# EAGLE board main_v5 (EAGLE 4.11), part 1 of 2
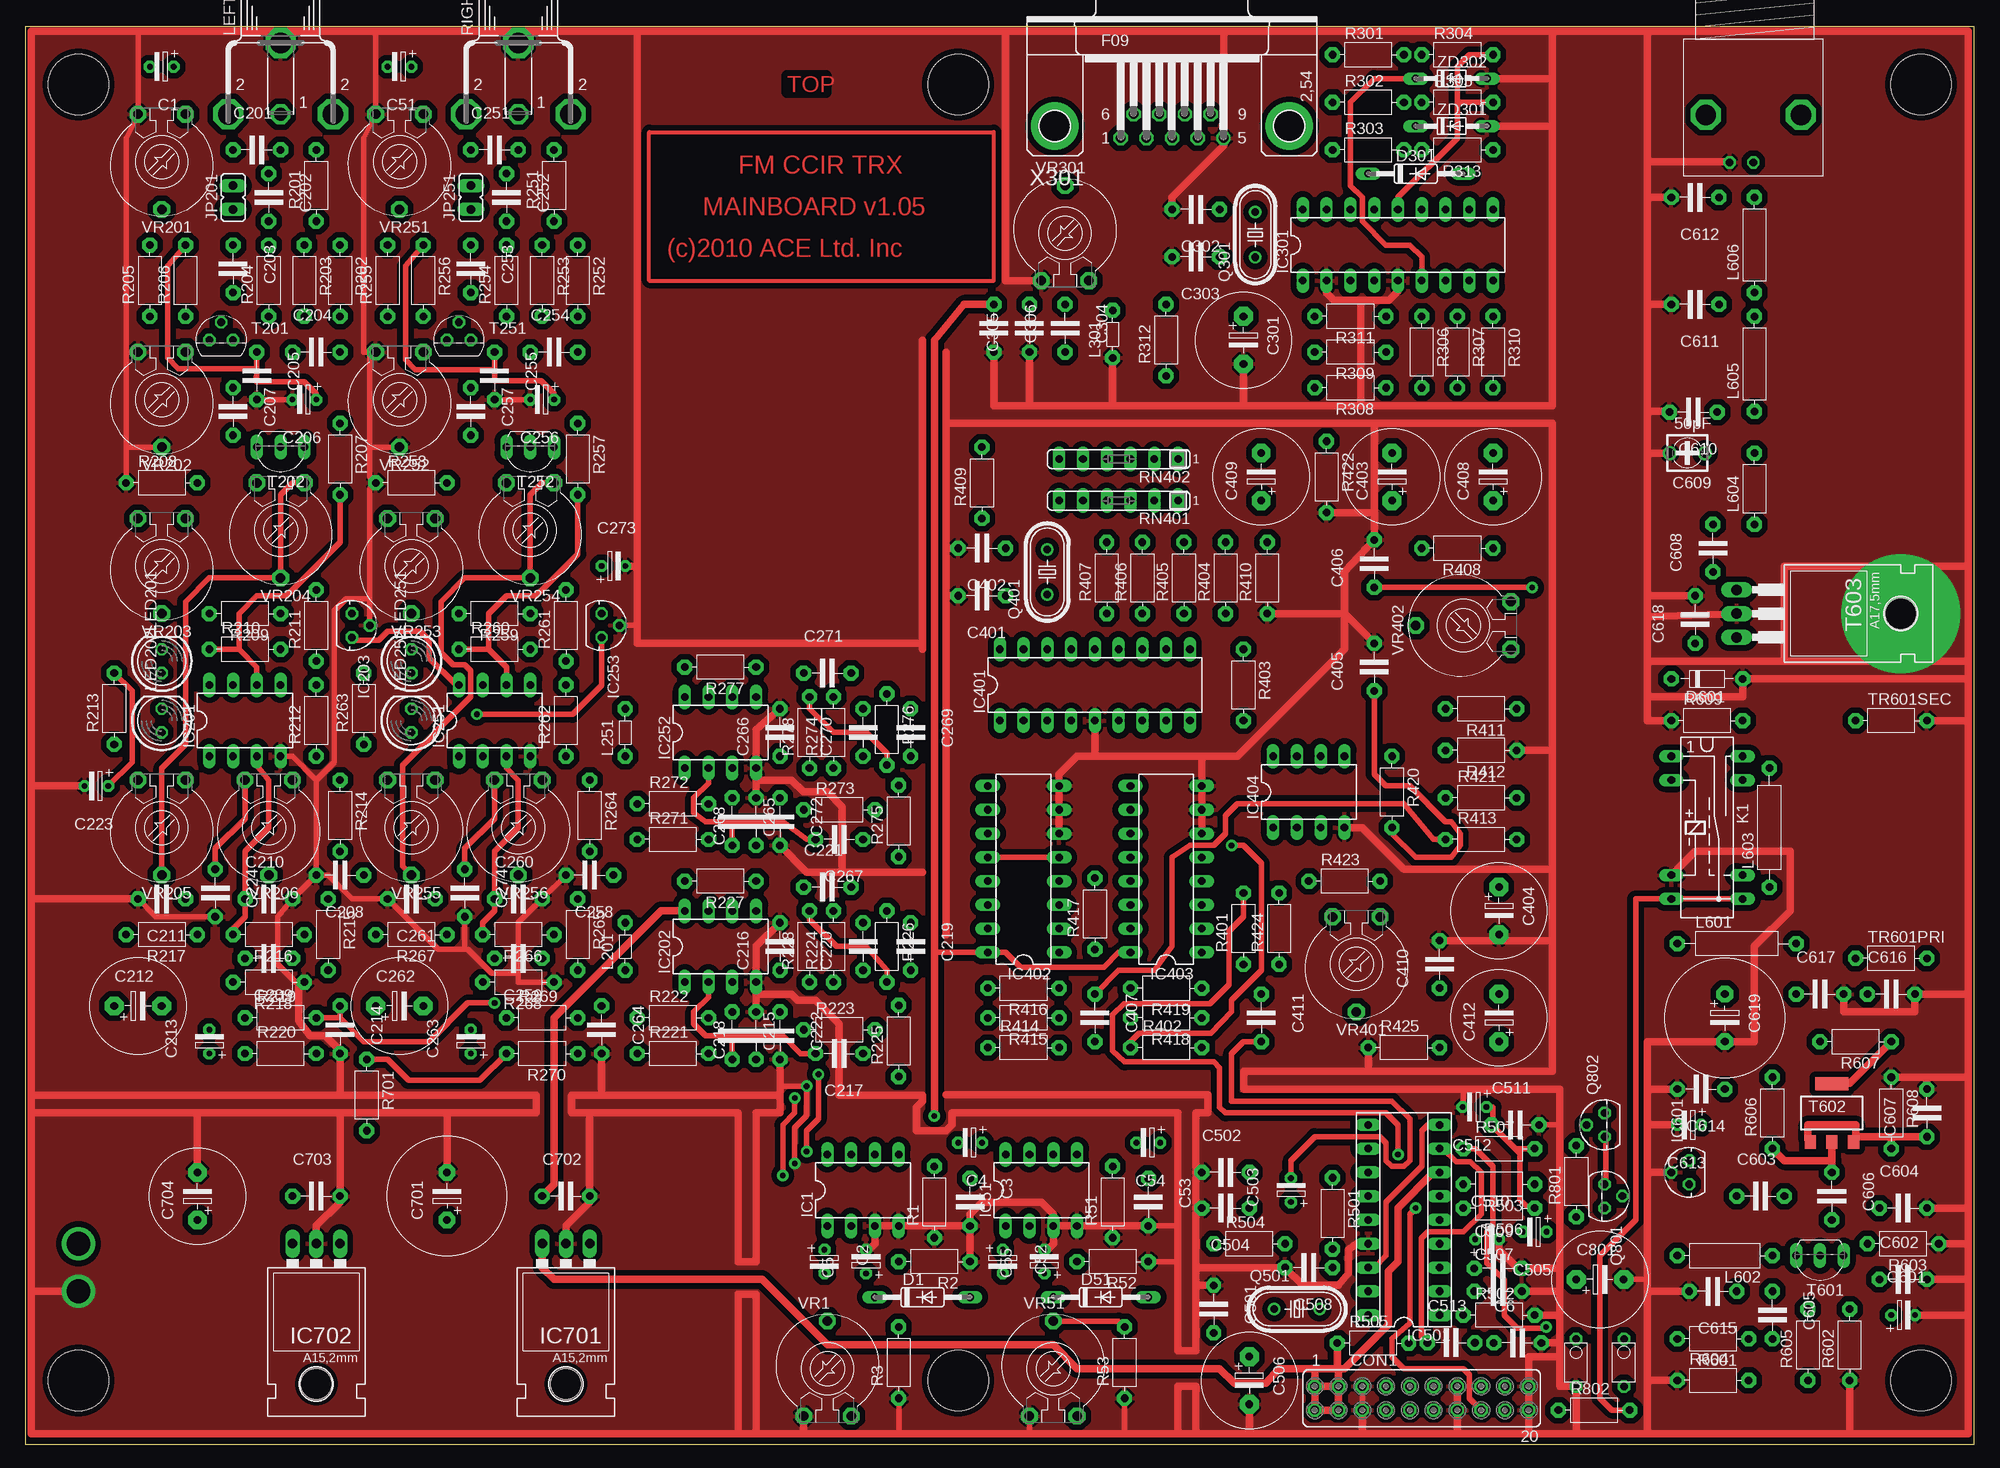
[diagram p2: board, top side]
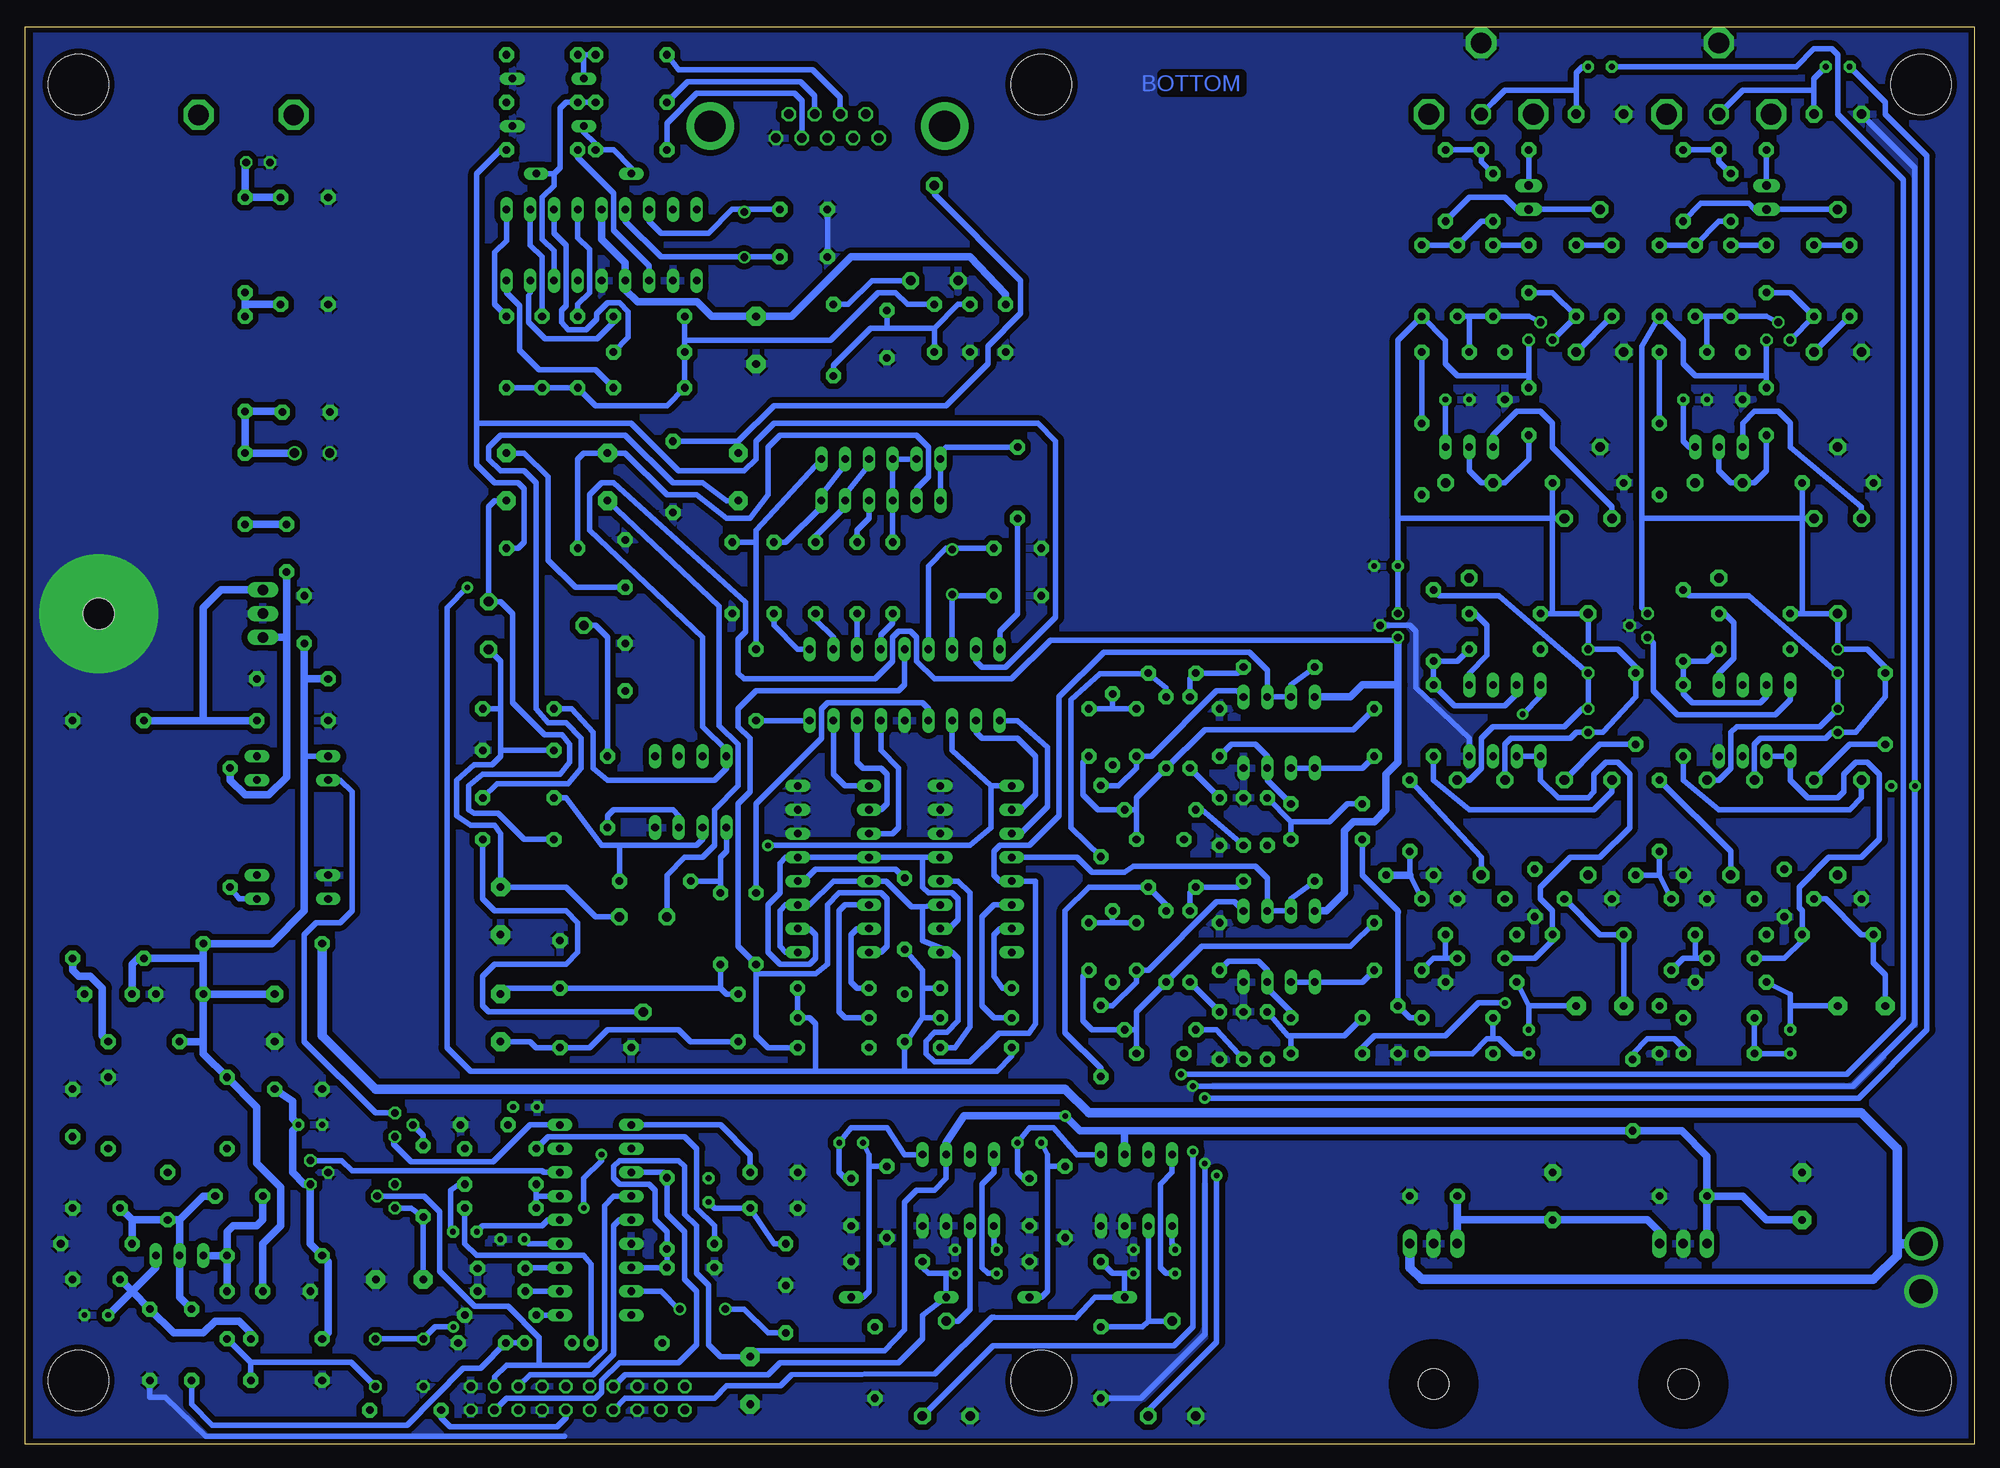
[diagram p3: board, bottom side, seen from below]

Size 208.26 x 151.44 mm. Coordinates in mm from the lower left corner, seen from the top.
Outline: 0,0 208.26,0 208.26,151.44 0,151.44 0,0
Copper layers (1*16): Top 0.035mm / dielectric 1.5mm / Bottom 0.035mm
Design rules "TRIDA5": minimum track width 10mil, minimum drill 24mil, track to track 12mil, track to pad 9mil, pad to pad 11mil, via to via 12mil, smd to smd 12mil, copper to edge 8mil, drill to drill 12mil, minimum pad ring 10mil, minimum via ring 12mil, stop-mask expansion 4mil, vias tented up to drill 0mil, thermal gap 10mil
Holes 6.45 mm at 99.69,6.82 5.71,6.82 202.56,145.25 202.56,6.82 5.71,145.25 99.69,145.25

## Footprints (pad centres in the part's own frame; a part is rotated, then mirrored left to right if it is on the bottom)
ES-2,5 = drill 0.61 pad 1.27 octagon: 1 -1.27,0; 2 1.27,0
C-5 = drill 0.813 pad 1.6 octagon: 1 -2.54,0; 2 2.54,0
ES-5 = drill 0.813 pad 2.007 octagon: 1 -2.54,0; 2 2.54,0
3008 = drill 1 round: + -1.875,0; - 1.875,0
ES-5L = drill 0.813 pad 1.778 octagon: 1 0,0; 2 5.08,0
FE10-2 = drill 0.914 octagon: 1 -11.43,1.27; 2 -11.43,-1.27; 3 -8.89,1.27; 4 -8.89,-1.27; 5 -6.35,1.27; 6 -6.35,-1.27; 7 -3.81,1.27; 8 -3.81,-1.27; 9 -1.27,1.27; 10 -1.27,-1.27; 11 1.27,1.27; 12 1.27,-1.27; 13 3.81,1.27; 14 3.81,-1.27; 15 6.35,1.27; 16 6.35,-1.27; 17 8.89,1.27; 18 8.89,-1.27; 19 11.43,1.27; 20 11.43,-1.27
DO35-10 = drill 0.813 long: A 5.08,0; C -5.08,0
D-7,5 = drill 0.813 pad 1.6 octagon: 1 -3.81,0; 2 3.81,0
DIL08 = drill 0.813 long: 1 -3.81,-3.81; 2 -1.27,-3.81; 3 1.27,-3.81; 4 3.81,-3.81; 5 3.81,3.81; 6 1.27,3.81; 7 -1.27,3.81; 8 -3.81,3.81
78LXX = drill 0.813 octagon: GND 0,1.905; IN 1.27,0; OUT -1.27,0
DIL18 = drill 0.813 long: 1 -10.16,-3.81; 2 -7.62,-3.81; 3 -5.08,-3.81; 4 -2.54,-3.81; 5 0,-3.81; 6 2.54,-3.81; 7 5.08,-3.81; 8 7.62,-3.81; 9 10.16,-3.81; 10 10.16,3.81; 11 7.62,3.81; 12 5.08,3.81; 13 2.54,3.81; 14 0,3.81; 15 -2.54,3.81; 16 -5.08,3.81; 17 -7.62,3.81; 18 -10.16,3.81
DIL16 = drill 0.813 long: 1 -8.89,-3.81; 2 -6.35,-3.81; 3 -3.81,-3.81; 4 -1.27,-3.81; 5 1.27,-3.81; 6 3.81,-3.81; 7 6.35,-3.81; 8 8.89,-3.81; 9 8.89,3.81; 10 6.35,3.81; 11 3.81,3.81; 12 1.27,3.81; 13 -1.27,3.81; 14 -3.81,3.81; 15 -6.35,3.81; 16 -8.89,3.81
SOCKED-18 = drill 0.813 long: 1 -10.16,-3.81; 2 -7.62,-3.81; 3 -5.08,-3.81; 4 -2.54,-3.81; 5 0,-3.81; 6 2.54,-3.81; 7 5.08,-3.81; 8 7.62,-3.81; 9 10.16,-3.81; 10 10.16,3.81; 11 7.62,3.81; 12 5.08,3.81; 13 2.54,3.81; 14 0,3.81; 15 -2.54,3.81; 16 -5.08,3.81; 17 -7.62,3.81; 18 -10.16,3.81
78XXL = drill 1.016 long: GND 0,-3.81; IN -2.54,-3.81; OUT 2.54,-3.81 | hole 3.302: 0,11.176
JP1 = drill 0.914 long: 1 0,-1.27; 2 0,1.27
RR1U = drill 0.813 long: 1 -7.62,-3.81; 2 -5.08,-3.81; 6 5.08,-3.81; 7 7.62,-3.81; 8 7.62,3.81; 9 5.08,3.81; 13 -5.08,3.81; 14 -7.62,3.81
L-5 = drill 0.813 pad 1.6 octagon: 1 -2.54,0; 2 2.54,0
L-12,5 = drill 0.813 pad 1.6 octagon: 1 -6.35,0; 2 6.35,0
L-10 = drill 0.813 pad 1.6 octagon: 1 -5.08,0; 2 5.08,0
L-7,5 = drill 0.813 pad 1.6 octagon: 1 -3.81,0; 2 3.81,0
LED5MM = drill 0.813 octagon: A -1.27,0; K 1.27,0
TOBU3 = drill 1.397 octagon: 1 0,-2.54 | drill 2.21 octagon: 2 5.588,-2.54; 2@1 -5.588,-2.54; 2@2 0,5.08
HC49/S = drill 0.813 round: 1 -2.413,0; 2 2.413,0
HC49U-V = drill 0.813 round: 1 -2.413,0; 2 2.413,0
TO92 = drill 0.813 octagon: 1 1.27,0; 2 0,1.905; 3 -1.27,0
R-7,5 = drill 0.813 pad 1.6 octagon: 1 -3.81,0; 2 3.81,0
SIL6 = drill 0.813 long: 1 -6.35,0; 2 -3.81,0; 3 -1.27,0; 4 1.27,0; 5 3.81,0; 6 6.35,0
TO92-EBC = drill 0.813 long: B 0,-1.27; C -2.54,-1.27; E 2.54,-1.27
TO92-CEB = drill 0.813 long: B -2.54,0; C 2.54,0; E 0,0
SOT223 = smd 1.2 x 1.4: 1 -2.311,-3.099; 2 0,-3.099; 3 2.311,-3.099 | smd 3.5 x 1.4: 4 0,3.099
TO220AH = drill 1.118 long: 1 -2.54,-6.35; 2 0,-6.35; 3 2.54,-6.35 | hole 3.302: 0,11.176
BNC-Z50RW = drill 2.184 octagon: P$1 0,-5.08; P$2 0,5.08 | drill 0.813 octagon: P$3 5.08,0; P$4 5.08,-2.54
BB1X = drill 0.813 octagon: P$1 -2.54,0; P$2 2.54,0
PT-10 = drill 1.016 pad 1.778 octagon: 1 -2.54,-5.08; 2 2.54,-5.08; 3 0,5.08
F09HP = drill 1.016 octagon: 1 -5.486,-1.27; 2 -2.743,-1.27; 3 0,-1.27; 4 2.743,-1.27; 5 5.486,-1.27; 6 -4.115,1.27; 7 -1.372,1.27; 8 1.372,1.27; 9 4.115,1.27 | drill 3.302 pad 5.08 round: G1 -12.522,0; G2 12.522,0
DO34Z7 = drill 0.813 long: A 3.81,0; C -3.81,0

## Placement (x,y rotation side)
C1  0,47uF  [ES-2,5]  14.6,147.16 180 top
C2  10uF  [ES-2,5]  85.4,19.52 270 top
C3  47nF  [C-5]  100.96,25.87 270 top
C4  4,7uF  [ES-2,5]  100.96,32.22 180 top
C5  0,1uF  [ES-2,5]  89.85,19.52 90 top
C6  100nF  [C-5]  159.46,10.83 0 top
C51  0,47uF  [ES-2,5]  40,147.16 180 top
C52  10uF  [ES-2,5]  104.45,19.52 270 top
C53  47nF  [C-5]  120.01,25.87 270 top
C54  4,7uF  [ES-2,5]  120.01,32.22 180 top
C55  0,1uF  [ES-2,5]  108.9,19.52 90 top
C201  4,7n  [C-5]  24.76,138.26 0 top
C202  470n  [C-5]  26.03,133.19 270 top
C203  4,7n  [C-5]  22.22,125.56 270 top
C204  330n  [C-5]  31.11,116.67 0 top
C205  10n  [C-5]  24.76,114.14 270 top
C206  10uF  [ES-2,5]  29.84,111.59 180 top
C207  22n  [C-5]  22.22,110.33 270 top
C208  330p  [C-5]  33.65,60.79 180 top
C209  470p  [C-5]  26.03,51.9 180 top
C210  82p  [C-5]  26.03,58.25 0 top
C211  10n  [C-5]  14.6,58.25 180 top
C212  220uF  [ES-5]  12.06,46.82 0 top
C213  220uF  [ES-2,5]  19.68,43.01 90 top
C214  560p  [C-5]  33.65,44.28 270 top
C215  2n7  [C-5]  75.56,43.65 270 top
C216  22p  [C-5]  80.64,53.17 90 top
C217  4n7  [C-5]  86.99,41.74 180 top
C218  10n  [C-5]  78.1,43.65 90 top
C219  270p  [C-5]  94.61,53.17 270 top
C220  270p  [C-5]  89.53,53.17 90 top
C221  560p  [C-5]  85.72,59.52 0 top
C222  100n  [C-5]  80.64,43.65 270 top
C223  220uF  [ES-2,5]  7.62,70.32 180 top
C224  10n  [C-5]  20.31,58.89 270 top
C251  4,7n  [C-5]  50.16,138.26 0 top
C252  470n  [C-5]  51.43,133.19 270 top
C253  4,7n  [C-5]  47.62,125.56 270 top
C254  330n  [C-5]  56.51,116.67 0 top
C255  10n  [C-5]  50.16,114.14 270 top
C256  10uF  [ES-2,5]  55.24,111.59 180 top
C257  22n  [C-5]  47.62,110.33 270 top
C258  330p  [C-5]  60.32,60.79 180 top
C259  470p  [C-5]  52.7,51.9 180 top
C260  82p  [C-5]  52.7,58.25 0 top
C261  10n  [C-5]  41.27,58.25 180 top
C262  220uF  [ES-5]  40,46.82 0 top
C263  220uF  [ES-2,5]  47.62,43.01 90 top
C264  560p  [C-5]  61.59,44.28 270 top
C265  2n7  [C-5]  75.56,66.51 270 top
C266  22p  [C-5]  80.64,76.04 90 top
C267  4n7  [C-5]  86.99,64.61 180 top
C268  10n  [C-5]  78.1,66.51 90 top
C269  270p  [C-5]  94.61,76.04 270 top
C270  270p  [C-5]  89.53,76.04 90 top
C271  560p  [C-5]  85.72,82.39 0 top
C272  100n  [C-5]  80.64,66.51 270 top
C273  220uF  [ES-2,5]  62.86,93.81 0 top
C274  10n  [C-5]  46.98,58.89 270 top
C301  220uF  [ES-5]  130.17,117.95 270 top
C302  27p  [C-5]  125.09,131.91 180 top
C303  27p  [C-5]  125.09,126.84 180 top
C304  10nF  [C-5]  111.12,119.22 270 top
C305  22nF  [C-5]  107.31,119.22 90 top
C306  100nF  [C-5]  103.5,119.22 270 top
C401  47p  [C-5]  102.23,90.64 180 top
C402  47p  [C-5]  102.23,95.72 180 top
C403  100uF  [ES-5]  146.04,103.34 90 top
C404  100uF  [ES-5]  157.47,56.98 270 top
C405  22p  [C-5]  144.14,83.02 90 top
C406  82p  [C-5]  144.14,94.07 90 top
C407  100nF  [C-5]  114.3,45.55 270 top
C408  100uF  [ES-5]  156.84,103.34 90 top
C409  100uF  [ES-5]  132.07,103.34 90 top
C410  270p  [C-5]  151.12,51.27 90 top
C411  100nF  [C-5]  132.07,45.55 270 top
C412  220uF  [ES-5]  157.47,45.55 90 top
C501  22pF  [C-5]  126.99,14.44 270 top
C502  10nF  [C-5]  128.27,29.05 0 top
C503  0.22uF  [ES-2,5]  135.25,27.14 90 top
C504  100pF  [C-5]  128.27,25.23 180 top
C505  10uF  [ES-2,5]  161.28,22.7 180 top
C506  220uF  [ES-5]  130.81,6.82 270 top
C507  2.2nF  [C-5]  157.38,16.34 0 top
C508  100nF  [C-5]  137.16,18.89 180 top
C509  10nF  [C-5]  157.38,18.79 0 top
C510  47uF  [ES-2,5]  156.2,21.9 0 top
C511  100pF  [C-5]  159.22,34.12 0 top
C512  0.47uF  [ES-2,5]  154.86,36.03 180 top
C513  1nF  [C-5]  152.36,10.85 0 top
C601  10uF  [ES-2,5]  200.66,13.8 0 top
C602  10nF  [C-5]  200.66,17.62 0 top
C603  15pF  [C-5]  185.41,26.5 0 top
C604  10pF  [C-5]  200.66,25.23 0 top
C605  1nF  [C-5]  186.69,13.8 270 top
C606  22pF  [C-5]  193.03,26.5 270 top
C607  10nF  [C-5]  203.19,35.39 90 top
C608  10nF  [C-5]  180.34,95.72 90 top
C609  50pF  [3008]  177.6,105.88 180 top
C610  47pF  [C-5]  178.24,110.26 180 top
C611  33pF  [C-5]  178.43,121.76 180 top
C612  15pF  [C-5]  178.43,133.19 180 top
C613  10uF  [ES-2,5]  177.79,34.12 180 top
C614  10nF  [C-5]  179.06,37.93 180 top
C615  100nF  [C-5]  180.34,16.34 180 top
C616  10nF  [C-5]  199.38,48.09 0 top
C617  10nF  [C-5]  191.76,48.09 0 top
C618  10nF  [C-5]  178.43,88.1 90 top
C619  470uF  [ES-5L]  181.6,48.09 270 top
C701  470uF  [ES-5L]  45.08,23.96 90 top
C702  10n  [C-5]  57.78,26.5 0 top
C703  100nF  [C-5]  31.11,26.5 0 top
C704  220uF  [ES-5]  18.41,26.5 90 top
C801  330uF  [ES-5]  168.27,17.62 0 top
CON1  [FE10-2]  149.22,4.92 0 top
D1  1N4148  [DO35-10]  95.88,15.71 0 top
D51  1N4148  [DO35-10]  114.93,15.71 0 top
D301  1N4148  [DO35-10]  148.59,135.72 0 top
D601  SB260  [D-7,5]  179.7,81.75 180 top
IC1  LM386N  [DIL08]  89.53,27.14 0 top
IC51  LM386N  [DIL08]  108.58,27.14 0 top
IC201  TLC272P  [DIL08]  23.49,77.31 0 top
IC202  TLC272P  [DIL08]  74.29,53.17 0 top
IC203  78L05  [78LXX]  34.92,87.47 270 top
IC251  TLC272P  [DIL08]  50.16,77.31 0 top
IC252  TLC272P  [DIL08]  74.29,76.04 0 top
IC253  78L05  [78LXX]  61.59,87.47 270 top
IC301  MRDS192  [DIL18]  146.68,128.1 0 top
IC401  PIC18F1220-I/P  [DIL18]  114.3,81.12 0 top
IC402  74HC4053  [DIL16]  106.67,61.43 90 top
IC403  74HC4053  [DIL16]  121.91,61.43 90 top
IC404  TLC272P  [DIL08]  137.16,69.69 0 top
IC501  SAA1057  [SOCKED-18]  147.31,23.96 90 top
IC601  LM78L09  [78LXX]  177.79,29.05 90 top
IC701  7812  [78XXL]  57.78,17.62 180 top
IC702  7805  [78XXL]  31.11,17.62 180 top
JP201  [JP1]  22.22,133.19 0 top
JP251  [JP1]  47.62,133.19 0 top
K1  DIP05-1C90-51L  [RR1U]  179.7,65.88 270 top
L201  15mH  [L-5]  64.13,53.17 90 top
L251  15mH  [L-5]  64.13,76.04 90 top
L301  330uH  [L-5]  116.2,118.58 90 top
L601  1uH  [L-12,5]  182.88,53.49 0 top
L602  3,5z@7mm  [L-10]  181.6,20.16 180 top
L603  1uH  [L-12,5]  186.37,65.88 90 top
L604  2,5z@6mm  [L-7,5]  184.78,102.07 90 top
L605  3,5z@6mm  [L-10]  184.78,115.41 90 top
L606  3,5z@6mm  [L-10]  184.78,128.1 90 top
LED201  [LED5MM]  14.6,83.66 90 top
LED202  [LED5MM]  14.6,77.31 90 top
LED251  [LED5MM]  41.27,83.66 90 top
LED252  [LED5MM]  41.27,77.31 90 top
LEFT  CON2  [TOBU3]  27.3,144.61 0 top
Q301  4.332  [HC49/S]  131.44,129.22 90 top
Q401  7.3728  [HC49U-V]  109.21,93.18 90 top
Q501  4MHz  [HC49U-V]  135.88,14.44 0 top
Q801  BC547A  [TO92]  168.75,26.5 270 top
Q802  BC547A  [TO92]  168.75,34.12 90 top
R1  2k2  [R-7,5]  97.15,25.87 90 top
R2  1M  [R-7,5]  97.15,19.52 180 top
R3  180R  [R-7,5]  93.34,8.72 90 top
R51  2k2  [R-7,5]  116.2,25.87 90 top
R52  1M  [R-7,5]  116.2,19.52 180 top
R53  180R  [R-7,5]  117.47,8.72 90 top
R201  10k  [R-7,5]  31.11,134.45 90 top
R202  1k  [R-7,5]  33.65,124.3 270 top
R203  10k  [R-7,5]  29.84,124.3 270 top
R204  1M  [R-7,5]  26.03,124.3 90 top
R205  33k  [R-7,5]  13.33,124.3 90 top
R206  1M  [R-7,5]  17.14,124.3 90 top
R207  18k  [R-7,5]  33.65,105.25 270 top
R208  470R  [R-7,5]  14.6,102.7 0 top
R209  33k  [R-7,5]  23.49,88.73 180 top
R210  1,5M  [R-7,5]  23.49,84.92 0 top
R211  470R  [R-7,5]  31.11,87.47 90 top
R212  470R  [R-7,5]  31.11,77.31 90 top
R213  270R  [R-7,5]  9.52,78.58 90 top
R214  33k  [R-7,5]  33.65,67.15 270 top
R215  33k  [R-7,5]  32.38,54.45 270 top
R216  33k  [R-7,5]  26.03,54.45 180 top
R217  470R  [R-7,5]  14.6,54.45 180 top
R218  33k  [R-7,5]  26.03,49.36 180 top
R219  39k  [R-7,5]  27.3,45.55 0 top
R220  2K  [R-7,5]  27.3,41.74 0 top
R221  39k  [R-7,5]  69.21,41.74 0 top
R222  39k  [R-7,5]  69.21,45.55 0 top
R223  1k  [R-7,5]  86.99,44.28 0 top
R224  30k  [R-7,5]  86.35,53.17 90 top
R225  30k  [R-7,5]  93.34,43.08 90 top
R226  16k  [R-7,5]  92.07,53.17 270 top
R227  47R  [R-7,5]  74.29,60.16 180 top
R228  680R  [R-7,5]  83.81,53.17 90 top
R251  10k  [R-7,5]  56.51,134.45 90 top
R252  1k  [R-7,5]  59.05,124.3 270 top
R253  10k  [R-7,5]  55.24,124.3 270 top
R254  1M  [R-7,5]  51.43,124.3 90 top
R255  33k  [R-7,5]  38.73,124.3 90 top
R256  1M  [R-7,5]  42.54,124.3 270 top
R257  18k  [R-7,5]  59.05,105.25 270 top
R258  470R  [R-7,5]  41.27,102.7 0 top
R259  33k  [R-7,5]  50.16,88.73 180 top
R260  1,5M  [R-7,5]  50.16,84.92 0 top
R261  470R  [R-7,5]  57.78,87.47 90 top
R262  470R  [R-7,5]  57.78,77.31 90 top
R263  270R  [R-7,5]  36.19,78.58 90 top
R264  33k  [R-7,5]  60.32,67.15 270 top
R265  33k  [R-7,5]  59.05,54.45 270 top
R266  33k  [R-7,5]  52.7,54.45 180 top
R267  470R  [R-7,5]  41.27,54.45 180 top
R268  33k  [R-7,5]  52.7,49.36 180 top
R269  39k  [R-7,5]  55.24,45.55 0 top
R270  2K  [R-7,5]  55.24,41.74 180 top
R271  39k  [R-7,5]  69.21,64.61 0 top
R272  39k  [R-7,5]  69.21,68.42 0 top
R273  1k  [R-7,5]  86.99,67.78 0 top
R274  30k  [R-7,5]  86.35,76.04 90 top
R275  30k  [R-7,5]  93.34,66.57 90 top
R276  16k  [R-7,5]  92.07,76.35 270 top
R277  47R  [R-7,5]  74.29,83.02 180 top
R278  680R  [R-7,5]  83.81,76.04 90 top
R301  680R  [R-7,5]  143.5,148.42 0 top
R302  680R  [R-7,5]  143.5,143.34 0 top
R303  680R  [R-7,5]  143.5,138.26 0 top
R304  4k7  [R-7,5]  153.03,148.42 0 top
R305  4k7  [R-7,5]  153.03,143.34 0 top
R306  1k  [R-7,5]  149.22,116.67 270 top
R307  3k9  [R-7,5]  153.03,116.67 270 top
R308  16k  [R-7,5]  141.6,112.87 180 top
R309  2k  [R-7,5]  141.6,116.67 180 top
R310  8k2  [R-7,5]  156.84,116.67 270 top
R311  33k  [R-7,5]  141.6,120.49 180 top
R312  820R  [R-7,5]  121.91,117.95 90 top
R313  10k  [R-7,5]  153.03,138.26 180 top
R401  10k  [R-7,5]  130.17,55.08 90 top
R402  1k  [R-7,5]  121.91,42.38 0 top
R403  2k  [R-7,5]  130.17,81.12 270 top
R404  2k  [R-7,5]  128.27,92.55 90 top
R405  2k  [R-7,5]  123.82,92.55 90 top
R406  2k  [R-7,5]  119.38,92.55 90 top
R407  2k  [R-7,5]  115.56,92.55 90 top
R408  2k  [R-7,5]  153.03,95.72 180 top
R409  2k  [R-7,5]  102.23,102.7 90 top
R410  2k  [R-7,5]  132.71,92.55 90 top
R411  2k  [R-7,5]  155.57,78.58 180 top
R412  2k  [R-7,5]  155.57,74.13 180 top
R413  39k  [R-7,5]  155.57,64.61 0 top
R414  160k  [R-7,5]  106.67,42.38 0 top
R415  10k  [R-7,5]  106.67,45.55 180 top
R416  82k  [R-7,5]  106.67,48.73 180 top
R417  330k  [R-7,5]  114.3,56.67 90 top
R418  39k  [R-7,5]  121.91,45.55 180 top
R419  20k  [R-7,5]  121.91,48.73 180 top
R420  10k  [R-7,5]  146.04,69.69 270 top
R421  10k  [R-7,5]  155.57,69.05 0 top
R422  1k  [R-7,5]  139.06,103.34 270 top
R423  20k  [R-7,5]  140.97,60.16 0 top
R424  470R  [R-7,5]  133.98,55.08 90 top
R425  10k  [R-7,5]  147.31,42.38 0 top
R501  10k  [R-7,5]  139.69,24.66 270 top
R502  1k  [R-7,5]  157.47,13.8 0 top
R503  4k7  [R-7,5]  157.47,27.78 180 top
R504  27k  [R-7,5]  130.81,21.43 0 top
R505  47k  [R-7,5]  144.01,10.82 0 top
R506  10k  [R-7,5]  157.47,25.23 180 top
R507  27k  [R-7,5]  157.47,31.59 0 top
R601  10k  [R-7,5]  180.34,11.27 180 top
R602  10k  [R-7,5]  194.94,10.63 90 top
R603  270R  [R-7,5]  200.66,21.43 180 top
R604  33k  [R-7,5]  180.34,6.82 0 top
R605  680R  [R-7,5]  190.5,10.63 90 top
R606  18k  [R-7,5]  186.69,35.39 90 top
R607  680R  [R-7,5]  195.57,43.01 180 top
R608  47R  [R-7,5]  199.38,35.39 270 top
R609  18R  [R-7,5]  179.7,77.31 0 top
R701  2K  [R-7,5]  36.51,37.3 270 top
R801  2k2  [R-7,5]  165.73,28.09 90 top
R802  820R  [R-7,5]  167.63,3.65 0 top
RIGHT  CON2  [TOBU3]  52.7,144.61 0 top
RN401  1k  [SIL6]  116.83,100.8 180 top
RN402  1k  [SIL6]  116.83,105.25 180 top
T201  BF245  [TO92]  20.95,117.95 0 top
T202  BC557B  [TO92-EBC]  27.3,105.25 180 top
T251  BF245  [TO92]  46.35,117.95 0 top
T252  BC557B  [TO92-EBC]  53.97,105.25 180 top
T601  BF240  [TO92-CEB]  191.76,20.16 180 top
T602  BFG135SMD  [SOT223]  193.03,35.39 0 top
T603  2SC1971AXIAL  [TO220AH]  189.22,88.73 270 top
TR601PRI  2z  [L-7,5]  199.38,51.9 0 top
TR601SEC  1z  [L-7,5]  199.38,77.31 0 top
U$6  BNC-Z50RW  [BNC-Z50RW]  184.65,142.01 270 top
U$7  BB109G  [BB1X]  170.83,8.72 270 top
U$8  BB109G  [BB1X]  165.71,8.71 270 top
VR1  100k  [PT-10]  85.72,8.09 0 top
VR51  100k  [PT-10]  109.85,8.09 0 top
VR201  5k  [PT-10]  14.6,136.99 180 top
VR202  5M  [PT-10]  14.6,111.59 180 top
VR203  1k  [PT-10]  14.6,93.81 180 top
VR204  5k  [PT-10]  27.3,97.62 180 top
VR205  500R  [PT-10]  14.6,65.88 180 top
VR206  5k  [PT-10]  26.03,65.88 180 top
VR251  5k  [PT-10]  40,136.99 180 top
VR252  5M  [PT-10]  40,111.59 180 top
VR253  1k  [PT-10]  41.27,93.81 180 top
VR254  5k  [PT-10]  53.97,97.62 180 top
VR255  500R  [PT-10]  41.27,65.88 180 top
VR256  5k  [PT-10]  52.7,65.88 180 top
VR301  500R  [PT-10]  111.12,129.38 0 top
VR401  5k  [PT-10]  142.23,51.27 180 top
VR402  5k  [PT-10]  153.66,87.47 90 top
X301  [F09HP]  122.55,140.8 0 top
ZD301  5V1  [DO34Z7]  152.39,140.8 0 top
ZD302  5V1  [DO34Z7]  152.39,145.88 0 top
